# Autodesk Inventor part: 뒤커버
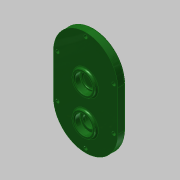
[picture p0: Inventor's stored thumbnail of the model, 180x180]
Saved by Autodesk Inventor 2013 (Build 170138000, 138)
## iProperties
Created: 2016-12
Part Number: 뒤커버
Material: 알루미늄 6061
Document SubType Name: Modeling
Designer: mduedu
Density: 2.71 g/cm^3
Mass: 236.33 g
Surface Area: 240.959 cm^2
Volume: 87.2065 cm^3
Author: mduedu
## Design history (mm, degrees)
sketch "스케치1"
  geometry: L1 (40, -25)-(40, 25); L2 (-40, 25)-(-40, -25); L3 (-40, -25)-(40, 25); L4 (40, -25)-(-40, 25); A1 r 40 centre (0, 25) between (40, 25) and (-40, 25); A2 r 40 centre (0, -25) between (-40, -25) and (40, -25); 1 further point
  constraints: 8 end point, 4 point on circle, 4 tangent, 2 centre point, 2 midpoint, 1 parallel, 1 vertical
  dimensions: "d0" = 130 dimension on A2 A1; "d2" = 80 distance between parallel lines of L1 L2
extrude "돌출1" new body sketch "스케치1" distance "d3" = 10; taper "d4" = 0 deg
sketch "스케치2"
  geometry: C1 r 14 at (0, 11); 1 further point
  constraints: 1 centre point, 1 vertical alignment
  dimensions: "d5" = 28 diameter of C1; "d6" = 11 distance of C1.centre point (0, 0)
extrude "돌출2" join sketch "스케치2" distance "d7" = 3; taper "d8" = 0 deg
sketch "스케치3"
  geometry: C1 r 14 at (0, -33.1); C2 r 14 at (0, 11) reference; 1 further point
  constraints: 1 centre point, 1 vertical alignment
  dimensions: "d9" = 28 diameter of C1; "d69" = 44.1 distance of C1.centre C2.centre
extrude "돌출3" join sketch "스케치3" distance "d11" = 3; taper "d12" = 0 deg
hole "구멍1" diameter "d15" = 22; stored, may be unused: countersink angle "d19" = 90 deg, drill point angle "d21" = 0 deg; dims "d13" = 10, "d14" = 10, "d16" = 6, "d17" = 4, "d18" = 2, "d20" = 7
hole "구멍2" diameter "d24" = 18; stored, may be unused: countersink angle "d28" = 90 deg, drill point angle "d30" = 0 deg; dims "d22" = 10, "d23" = 10, "d25" = 6, "d26" = 4, "d27" = 2, "d29" = 1
hole "구멍3" diameter "d33" = 22; stored, may be unused: countersink angle "d37" = 90 deg, drill point angle "d39" = 0 deg; dims "d31" = 10, "d32" = 10, "d34" = 6, "d35" = 4, "d36" = 2, "d38" = 7
sketch "스케치4"
  geometry: C1 r 14 at (0, -33.1) reference; C2 r 18 at (0, -33.1); 1 further point
  constraints: 1 centre point, 1 coincident
  dimensions: "d40" = 36 diameter of C2
extrude "돌출4" join sketch "스케치4" distance "d41" = 4; taper "d42" = 0 deg
hole "구멍4" diameter "d45" = 22; stored, may be unused: countersink angle "d49" = 90 deg, drill point angle "d51" = 0 deg; dims "d46" = 6, "d47" = 4, "d48" = 2, "d50" = 7.3, "d80" = 10, "d81" = 10
hole "구멍5" diameter "d54" = 15; stored, may be unused: countersink angle "d58" = 90 deg, drill point angle "d60" = 0 deg; dims "d52" = 10, "d53" = 10, "d55" = 6, "d56" = 4, "d57" = 2, "d59" = 7
fillet "모깎기1" dims "d61" = 0.3
fillet "모깎기2" dims "d62" = 2
chamfer "모따기1" distance "d63" = 1; stored, may be unused: second distance "d64" = 2, angle "d65" = 45 deg
chamfer "모따기2" distance "d82" = 0.7; stored, may be unused: second distance "d83" = 2, angle "d84" = 30 deg
fillet "모깎기3" dims "d66" = 2
fillet "모깎기4" dims "d67" = 2
fillet "모깎기5" dims "d68" = 2
sketch "스케치5"
  geometry: L1 (-40, 25)-(-40, -25) reference; L2 (40, -25)-(40, 25) reference; L3 (35, 25)-(35, -25); L4 (-35, -25)-(-35, 25); A1 r 40 centre (0, 25) between (40, 25) and (-40, 25) reference; A2 r 40 centre (0, -25) between (-40, -25) and (40, -25) reference; A3 r 35 centre (0, 25) between (35, 25) and (-35, 25); A4 r 35 centre (0, -25) between (-35, -25) and (35, -25); 2 further points
  constraints: 5 point on circle, 4 end point, 2 centre point, 1 vertical alignment, 3 other
  dimensions: "d70" = 5 distance between parallel lines of L2 L3
sketch "스케치6"
  geometry: 1 further point
  constraints: 1 other
hole "구멍6" sketch "스케치6" at (0, 60) diameter "d71" = 4.5; stored, may be unused: countersink angle "d75" = 90 deg, drill point angle "d77" = 0 deg; dims "d72" = 6, "d73" = 8, "d74" = 4.6, "d76" = 8
node "솔리드1"
pattern_linear "직사각형 패턴1"
